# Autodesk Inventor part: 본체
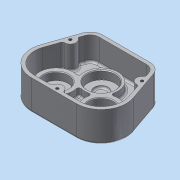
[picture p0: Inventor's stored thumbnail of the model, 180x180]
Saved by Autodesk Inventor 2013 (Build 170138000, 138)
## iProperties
Created: 2014-12
Part Number: 본체
Material: 알루미늄 6061
Document SubType Name: Modeling
Designer: Administrator
Density: 2.71 g/cm^3
Mass: 613.436 g
Surface Area: 665.181 cm^2
Volume: 226.36 cm^3
Author: Administrator
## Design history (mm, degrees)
sketch "스케치1"
  geometry: L1 (-47, 36)-(47, 36); L2 (0, 0)-(-32.527, -32.527); L3 (0, 0)-(32.527, -32.527); L4 (0, 0)-(0, -73.351); L5 (-47, 36)-(-66.565, -20.803); L6 (47, 36)-(66.565, -20.803); L7 (-32.527, -68.527)-(32.527, -68.527); A1 r 46 centre (0, 0) between (-32.527, -32.527) and (32.527, -32.527); A2 r 36 centre (-32.527, -32.527) between (-66.565, -20.803) and (-32.527, -68.527); A3 r 36 centre (32.527, -32.527) between (32.527, -68.527) and (66.565, -20.803); A4 r 36 centre (32.527, -32.527) between (-0.86, -45.992) and (0, -47.954); 3 further points
  constraints: 14 end point, 9 point on circle, 4 centre point, 4 tangent, 3 coincident, 2 vertical alignment, 1 equal radius, 1 horizontal, 1 midpoint, 1 parallel, 1 point on line
  dimensions: "d0" = 94 distance of L1.start L1.end; "d2" = 92 diameter of A1; "d4" = 45 deg angle of L4 L2; "d5" = 45 deg angle of L4 L3; "d8" = 36 distance from line of point (0, 0) L1; "d9" = 36 radius of A2
extrude "돌출1" new body sketch "스케치1" distance "d13" = 44; taper "d14" = 0 deg
fillet "모깎기1" dims "d15" = 18
feature "쉘1" dims "d16" = 5
sketch "스케치12"
  geometry: L1 (0, 0)-(68.324, 0) reference; L2 (-27.675, -53.432)-(-12.291, -8.767) reference; L3 (66.689, -94.527)-(1.635, -94.527) reference; L4 (80.615, -8.767)-(95.999, -53.432) reference; A1 r 13 centre (68.324, -13) between (80.615, -8.767) and (68.324, 0) reference; A2 r 13 centre (0, -13) between (0, 0) and (-12.291, -8.767) reference; A3 r 31 centre (1.635, -63.527) between (-27.675, -53.432) and (1.635, -94.527) reference; A4 r 31 centre (66.689, -63.527) between (66.689, -94.527) and (95.999, -53.432) reference; 1 further point
extrude "돌출10" join sketch "스케치12" distance "d64" = 5; taper "d65" = 0 deg
sketch "스케치3"
  geometry: C1 r 20 at (-32.527, -32.527); C2 r 20 at (32.527, -32.527); A1 r 36 centre (-32.527, -32.527) between (-66.565, -20.803) and (-32.527, -68.527) reference; A2 r 36 centre (32.527, -32.527) between (32.527, -68.527) and (66.565, -20.803) reference; 1 further point
  constraints: 2 centre point, 2 coincident
  dimensions: "d22" = 40 diameter of C1; "d23" = 40 diameter of C2
extrude "돌출3" join sketch "스케치3" distance "d24" = 7; taper "d25" = -10 deg
sketch "스케치4"
  geometry: C1 r 18.766 at (0, 0) reference; C2 r 15 at (0, 0); 1 further point
  constraints: 1 centre point, 1 coincident
  dimensions: "d26" = 30 diameter of C2
extrude "돌출4" cut sketch "스케치4" distance "d27" = 7; taper "d28" = 0 deg
sketch "스케치5"
  geometry: C1 r 18.766 at (0, 0) reference; C2 r 15 at (0, 0); 1 further point
  constraints: 1 centre point, 1 coincident
  dimensions: "d29" = 30 diameter of C2
extrude "돌출5" cut sketch "스케치5" distance "d30" = 7; taper "d31" = 0 deg
sketch "스케치6"
  geometry: L1 (68.324, 5)-(0, 5) reference; L2 (100.726, -51.803)-(85.343, -7.138) reference; L3 (80.615, -8.767)-(95.999, -53.432) reference; A1 r 8 centre (85.862, -24) between (88.556, -16.467) and (92.623, -28.276)
  constraints: 2 point on circle, 2 point on line, 1 centre point
  dimensions: "d32" = 16 diameter of A1; "d33" = 29 distance from line of A1.centre L1; "d34" = 5 distance from line of L2 A1.centre
extrude "돌출6" join sketch "스케치6" distance "d35" = 39; taper "d36" = 0 deg
sketch "스케치7"
  geometry: L1 (68.324, 5)-(0, 5) reference; L2 (-17.019, -7.138)-(-32.403, -51.803) reference; A1 r 8 centre (-17.538, -24) between (-24.299, -28.276) and (-20.232, -16.467)
  constraints: 2 point on circle, 2 point on line, 1 centre point
  dimensions: "d37" = 16 diameter of A1; "d38" = 29 distance from line of L1 A1.centre; "d39" = 5 distance from line of L2 A1.centre
extrude "돌출7" join sketch "스케치7" distance "d40" = 39; taper "d41" = 0 deg
sketch "스케치8"
  geometry: L1 (68.324, 5)-(0, 5) reference; L2 (1.635, -99.527)-(66.689, -99.527) reference; A1 r 8 centre (34.162, -94.527) between (40.407, -99.527) and (27.917, -99.527); 1 further point
  constraints: 2 point on circle, 2 point on line, 1 centre point, 1 midpoint, 1 vertical alignment
  dimensions: "d42" = 16 diameter of A1; "d43" = 5 distance from line of L2 A1.centre
extrude "돌출8" join sketch "스케치8" distance "d44" = 39; taper "d45" = 0 deg
sketch "스케치9"
  geometry: A1 r 8 centre (51.7, 7) between (49.095, 14.564) and (54.305, -0.564) reference; 1 further point
hole "구멍1" sketch "스케치9" at (51.7, 7) diameter "d46" = 4.134; stored, may be unused: countersink angle "d50" = 90 deg, drill point angle "d52" = 118 deg; dims "d47" = 20, "d48" = 4, "d49" = 2, "d51" = 23
sketch "스케치10"
  geometry: A1 r 8 centre (-51.7, 7) between (-54.305, -0.564) and (-49.095, 14.564) reference; A2 r 8 centre (0, -63.527) between (8, -63.527) and (-8, -63.527) reference; 1 further point
hole "구멍2" sketch "스케치10" at (-51.7, 7), (0, -63.527) diameter "d53" = 4.134; stored, may be unused: countersink angle "d57" = 90 deg, drill point angle "d59" = 118 deg; dims "d54" = 20, "d55" = 4, "d56" = 2, "d58" = 23
sketch "스케치15"
  geometry: C1 r 24 at (34.162, -31); C2 r 24 at (1.635, -63.527); C3 r 24 at (66.689, -63.527); A1 r 31 centre (66.689, -63.527) between (66.689, -94.527) and (95.999, -53.432) reference; A2 r 31 centre (1.635, -63.527) between (-27.675, -53.432) and (1.635, -94.527) reference; 1 further point
  constraints: 3 centre point, 3 coincident
  dimensions: "d66" = 48 diameter of C1; "d67" = 48 diameter of C2; "d68" = 48 diameter of C3
extrude "돌출11" join sketch "스케치15" distance "d69" = 11; taper "d70" = 0 deg
sketch "스케치16"
  geometry: C1 r 20 at (34.162, -31); A1 r 24 centre (34.162, -31) between (55.273, -42.416) and (13.051, -42.416) reference
  constraints: 1 centre point, 1 coincident
  dimensions: "d71" = 40 diameter of C1
extrude "돌출12" cut sketch "스케치16" distance "d72" = 12; taper "d73" = 0 deg
sketch "스케치17"
  geometry: C1 r 17.5 at (1.635, -63.527); C2 r 17.5 at (66.689, -63.527); A1 r 24 centre (66.689, -63.527) between (45.578, -52.111) and (55.273, -42.416) reference; A2 r 24 centre (1.635, -63.527) between (13.051, -42.416) and (22.746, -52.111) reference
  constraints: 2 centre point, 2 coincident
  dimensions: "d74" = 35 diameter of C1; "d75" = 35 diameter of C2
extrude "돌출13" cut sketch "스케치17" distance "d76" = 11; taper "d77" = 0 deg
sketch "스케치18"
  geometry: C1 r 15 at (0, 0) reference; C2 r 7.75 at (0, 0); 1 further point
  constraints: 1 centre point, 1 coincident
  dimensions: "d78" = 15.5 diameter of C2
extrude "돌출14" cut sketch "스케치18" stored distance "d79" = 11; taper "d80" = 0 deg
sketch "스케치19"
  geometry: C1 r 15 at (0, 0) reference; C2 r 7.75 at (0, 0); 1 further point
  constraints: 1 centre point, 1 coincident
  dimensions: "d81" = 15.5 diameter of C2
extrude "돌출15" cut sketch "스케치19" stored distance "d82" = 11; taper "d83" = 0 deg
sketch "스케치20"
  geometry: C1 r 20 at (0, 0) reference; C2 r 10 at (0, 0)
  constraints: 1 centre point, 1 coincident
  dimensions: "d84" = 20 diameter of C2
extrude "돌출16" cut sketch "스케치20" distance "d85" = 3; taper "d86" = 0 deg
fillet "모깎기2" dims "d87" = 3
fillet "모깎기3" dims "d88" = 3
fillet "모깎기4" dims "d89" = 3
fillet "모깎기5" dims "d90" = 3
fillet "모깎기6" dims "d91" = 3
chamfer "모따기1" distance "d92" = 1; stored, may be unused: second distance "d93" = 2, angle "d94" = 45 deg
fillet "모깎기7" dims "d95" = 0.3
fillet "모깎기8" dims "d96" = 0.1
sketch "스케치21"
  geometry: L1 (-34.162, 33)-(34.162, 33) reference; L2 (34.162, 36)-(-34.162, 36) reference; 3 further points
  constraints: 1 midpoint, 1 vertical alignment, 1 other
  dimensions: "d97" = 30 distance from line of L2 point (0, 6)
feature "엠보싱1" sketch "스케치21" dims "d0" = 94, "d2" = 92, "d4" = 45 deg, "d5" = 45 deg, "d8" = 36, "d9" = 36, "d98" = 1, "d99" = 0
fillet "모깎기9" dims "d100" = 3
sketch "스케치22"
  geometry: 1 further point
fillet "모깎기10" dims "d101" = 3
node "솔리드1"
other parameters: "d6" = 72, "d7" = 72
